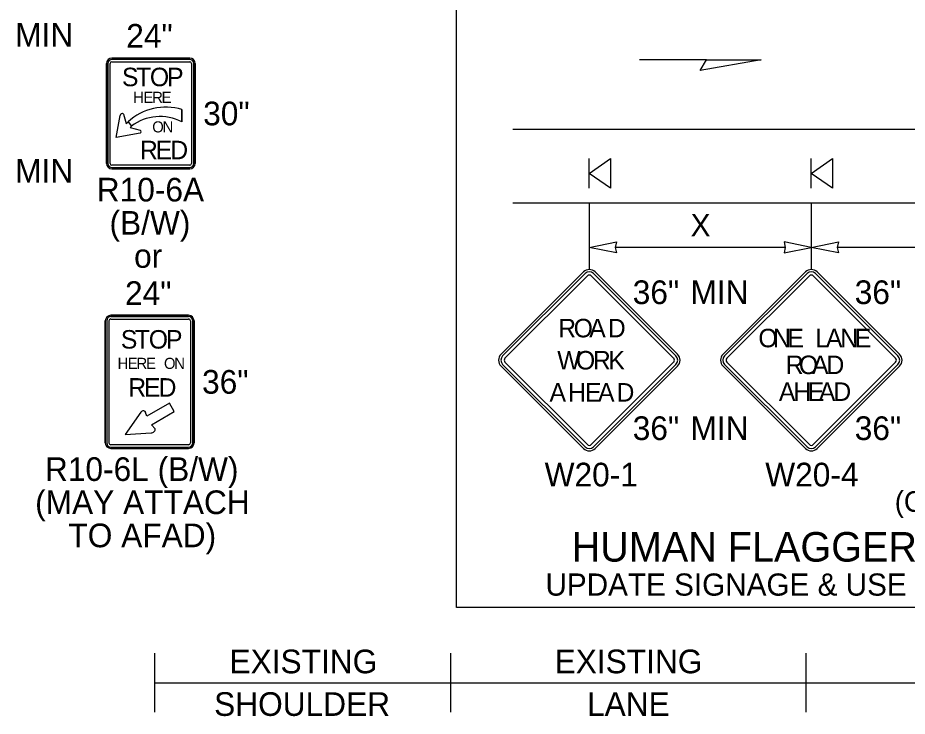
# Model space of a CAD drawing. Extents: x 99999.1 to 100095.7, y 99995 to 100010.7.
# Drawn here: x 100003.827 to 100006.832, y 100003.112 to 100005.473 of the extents above; entities that cross this region are included whole.
import ezdxf

# ---------------------------------------------------------------- set-up
doc = ezdxf.new("R2010")
doc.units = 0
for name, color, linetype in [('RD_ED_ShoulderPavedEdge', 7, 'Continuous'), ('RD_MK_LineEdgeWhite', 7, 'Continuous'), ('SH_DE_DetailHeading2Text', 7, 'Continuous'), ('TR_SN_ConstructionSigns', 7, 'Continuous'), ('TR_WZ_PortableSignMountBlk-Org', 7, 'Continuous'), ('TR_WZ_WorkZoneDetails', 7, 'Continuous'), ('TR_WZ_WorkZoneTextCurrent', 7, 'Continuous')]:
    doc.layers.add(name, color=color, linetype=linetype)

msp = doc.modelspace()

# ---------------------------------------------------------------- linework, layer by layer
at = {"layer": 'RD_ED_ShoulderPavedEdge'}
msp.add_line((100005.4994, 100004.8473), (100008.9925, 100004.8473), dxfattribs=at)
at = {"layer": 'RD_MK_LineEdgeWhite'}
msp.add_line((100005.4994, 100005.0973), (100008.9925, 100005.0973), dxfattribs=at)
at = {"layer": 'TR_SN_ConstructionSigns'}
for p, q in [((100004.4079, 100005.3373), (100004.1454, 100005.3373)), ((100004.1454, 100005.3373), (100004.4079, 100005.3373)), ((100004.4079, 100005.3373), (100004.1454, 100005.3373)), ((100004.1454, 100005.3373), (100004.4079, 100005.3373)), ((100004.4079, 100005.3326), (100004.1454, 100005.3326)), ((100004.1267, 100005.3186), (100004.1267, 100004.9811)), ((100004.1267, 100004.9811), (100004.1267, 100005.3186)), ((100004.1267, 100005.3186), (100004.1267, 100004.9811)), ((100004.1267, 100004.9811), (100004.1267, 100005.3186)), ((100004.1313, 100005.3186), (100004.1313, 100004.9811)), ((100004.1392, 100004.9811), (100004.1392, 100005.3186)), ((100004.1454, 100005.3248), (100004.4079, 100005.3248)), ((100004.4142, 100005.3186), (100004.4142, 100004.9811)), ((100004.422, 100004.9811), (100004.422, 100005.3186)), ((100004.4267, 100004.9811), (100004.4267, 100005.3186)), ((100004.4267, 100005.3186), (100004.4267, 100004.9811)), ((100004.4267, 100004.9811), (100004.4267, 100005.3186)), ((100004.4267, 100005.3186), (100004.4267, 100004.9811)), ((100004.1839, 100005.1479), (100004.1933, 100005.1154)), ((100004.3816, 100005.1635), (100004.3813, 100005.1216)), ((100004.3813, 100005.1216), (100004.3816, 100005.1635)), ((100004.1595, 100005.0686), (100004.1731, 100005.143)), ((100004.1933, 100005.1154), (100004.1996, 100005.1218)), ((100004.1996, 100005.1218), (100004.2113, 100005.1069)), ((100004.1996, 100005.1218), (100004.2113, 100005.1069)), ((100004.2113, 100005.1069), (100004.2066, 100005.1021)), ((100004.2066, 100005.1021), (100004.2408, 100005.0929)), ((100004.2406, 100005.0837), (100004.1595, 100005.0686)), ((100004.4079, 100004.9748), (100004.1454, 100004.9748)), ((100004.1454, 100004.967), (100004.4079, 100004.967)), ((100004.1454, 100004.9623), (100004.4079, 100004.9623)), ((100004.4079, 100004.9623), (100004.1454, 100004.9623)), ((100004.1454, 100004.9623), (100004.4079, 100004.9623)), ((100004.4079, 100004.9623), (100004.1454, 100004.9623)), ((100005.7382, 100004.6141), (100005.4598, 100004.3357)), ((100005.7437, 100004.6086), (100005.4653, 100004.3301)), ((100006.0509, 100004.3301), (100005.7724, 100004.6086)), ((100006.0564, 100004.3357), (100005.778, 100004.6141)), ((100006.4882, 100004.6141), (100006.2098, 100004.3357)), ((100006.4937, 100004.6086), (100006.2153, 100004.3301)), ((100006.8009, 100004.3301), (100006.5224, 100004.6086)), ((100006.8064, 100004.3357), (100006.528, 100004.6141)), ((100005.473, 100004.3224), (100005.7515, 100004.6008)), ((100005.7647, 100004.6008), (100006.0431, 100004.3224)), ((100006.223, 100004.3224), (100006.5015, 100004.6008)), ((100006.5147, 100004.6008), (100006.7931, 100004.3224)), ((100004.4041, 100004.4676), (100004.1416, 100004.4676)), ((100004.1416, 100004.4676), (100004.4041, 100004.4676)), ((100004.4041, 100004.4676), (100004.1416, 100004.4676)), ((100004.4041, 100004.4629), (100004.1416, 100004.4629)), ((100004.1416, 100004.4551), (100004.4041, 100004.4551)), ((100004.1229, 100004.4489), (100004.1229, 100004.0364)), ((100004.1229, 100004.0364), (100004.1229, 100004.4489)), ((100004.1229, 100004.4489), (100004.1229, 100004.0364)), ((100004.1276, 100004.4489), (100004.1276, 100004.0364)), ((100004.1354, 100004.0364), (100004.1354, 100004.4489)), ((100004.4104, 100004.4489), (100004.4104, 100004.0364)), ((100004.4182, 100004.0364), (100004.4182, 100004.4489)), ((100004.4229, 100004.0364), (100004.4229, 100004.4489)), ((100004.4229, 100004.4489), (100004.4229, 100004.0364)), ((100004.4229, 100004.0364), (100004.4229, 100004.4489)), ((100005.7515, 100004.0307), (100005.473, 100004.3092)), ((100006.0431, 100004.3092), (100005.7647, 100004.0307)), ((100006.5015, 100004.0307), (100006.223, 100004.3092)), ((100006.7931, 100004.3092), (100006.5147, 100004.0307)), ((100005.4598, 100004.2959), (100005.7382, 100004.0175)), ((100005.4653, 100004.3014), (100005.7437, 100004.023)), ((100005.7724, 100004.023), (100006.0509, 100004.3014)), ((100005.778, 100004.0175), (100006.0564, 100004.2959)), ((100006.2098, 100004.2959), (100006.4882, 100004.0175)), ((100006.2153, 100004.3014), (100006.4937, 100004.023)), ((100006.5224, 100004.023), (100006.8009, 100004.3014)), ((100006.528, 100004.0175), (100006.8064, 100004.2959)), ((100004.3396, 100004.1707), (100004.263, 100004.1265)), ((100004.356, 100004.1423), (100004.3396, 100004.1707)), ((100004.2424, 100004.1403), (100004.1898, 100004.0646)), ((100004.263, 100004.1265), (100004.2592, 100004.1391)), ((100004.2786, 100004.0976), (100004.356, 100004.1423)), ((100004.2909, 100004.0839), (100004.2786, 100004.0976)), ((100004.1898, 100004.0646), (100004.2776, 100004.0707)), ((100004.4041, 100004.0301), (100004.1416, 100004.0301)), ((100004.1416, 100004.0223), (100004.4041, 100004.0223)), ((100004.1416, 100004.0176), (100004.4041, 100004.0176)), ((100004.4041, 100004.0176), (100004.1416, 100004.0176)), ((100004.1416, 100004.0176), (100004.4041, 100004.0176))]:
    msp.add_line(p, q, dxfattribs=at)
for centre, radius, start, end in [((100004.1454, 100005.3186), 0.0187, 90, 180), ((100004.1454, 100005.3186), 0.0187, 90, 180), ((100004.1454, 100005.3186), 0.0187, 90, 180), ((100004.1454, 100005.3186), 0.0187, 90, 180), ((100004.1454, 100005.3186), 0.0141, 90, 180), ((100004.4079, 100005.3186), 0.0187, 0, 90), ((100004.4079, 100005.3186), 0.0187, 0, 90), ((100004.4079, 100005.3186), 0.0187, 0, 90), ((100004.4079, 100005.3186), 0.0187, 0, 90), ((100004.4079, 100005.3186), 0.0141, 0, 90), ((100004.1454, 100005.3186), 0.00625, 90, 180), ((100004.4079, 100005.3186), 0.00625, 0, 90), ((100004.3279, 100004.9804), 0.1909, 73.6434, 132.2131), ((100004.3279, 100004.9804), 0.1909, 73.6434, 132.2131), ((100004.3078, 100004.981), 0.1586, 62.4149, 127.4769), ((100004.3078, 100004.981), 0.1586, 62.4149, 127.4769), ((100004.1454, 100004.9811), 0.0187, 180, 270), ((100004.1454, 100004.9811), 0.0187, 180, 270), ((100004.1454, 100004.9811), 0.0187, 180, 270), ((100004.1454, 100004.9811), 0.0187, 180, 270), ((100004.1454, 100004.9811), 0.0141, 180, 270), ((100004.1454, 100004.9811), 0.00625, 180, 270), ((100004.4079, 100004.9811), 0.0187, 270, 0), ((100004.4079, 100004.9811), 0.0187, 270, 0), ((100004.4079, 100004.9811), 0.0187, 270, 0), ((100004.4079, 100004.9811), 0.0141, 270, 0), ((100004.4079, 100004.9811), 0.00625, 270, 0), ((100004.4079, 100004.9811), 0.0187, 270, 0), ((100005.7581, 100004.5942), 0.0281, 45, 135), ((100005.7581, 100004.5942), 0.0203, 45, 135), ((100006.5081, 100004.5942), 0.0281, 45, 135), ((100006.5081, 100004.5942), 0.0203, 45, 135), ((100005.7581, 100004.5942), 0.00937, 45, 135), ((100006.5081, 100004.5942), 0.00937, 45, 135), ((100004.1416, 100004.4489), 0.0187, 90, 180), ((100004.1416, 100004.4489), 0.0187, 90, 180), ((100004.1416, 100004.4489), 0.0187, 90, 180), ((100004.1416, 100004.4489), 0.0141, 90, 180), ((100004.1416, 100004.4489), 0.00625, 90, 180), ((100004.4041, 100004.4489), 0.0187, 0, 90), ((100004.4041, 100004.4489), 0.0187, 0, 90), ((100004.4041, 100004.4489), 0.0187, 0, 90), ((100004.4041, 100004.4489), 0.0141, 0, 90), ((100004.4041, 100004.4489), 0.00625, 0, 90), ((100005.4797, 100004.3158), 0.0281, 135, 225), ((100006.0365, 100004.3158), 0.0281, 315, 45), ((100006.2297, 100004.3158), 0.0281, 135, 225), ((100006.7865, 100004.3158), 0.0281, 315, 45), ((100005.4797, 100004.3158), 0.0203, 135, 225), ((100005.4797, 100004.3158), 0.00937, 135, 225), ((100006.0365, 100004.3158), 0.00937, 315, 45), ((100006.0365, 100004.3158), 0.0203, 315, 45), ((100006.2297, 100004.3158), 0.0203, 135, 225), ((100006.2297, 100004.3158), 0.00937, 135, 225), ((100006.7865, 100004.3158), 0.00937, 315, 45), ((100006.7865, 100004.3158), 0.0203, 315, 45), ((100004.1416, 100004.0364), 0.0187, 180, 270), ((100004.1416, 100004.0364), 0.0187, 180, 270), ((100004.1416, 100004.0364), 0.0187, 180, 270), ((100004.1416, 100004.0364), 0.0141, 180, 270), ((100004.1416, 100004.0364), 0.00625, 180, 270), ((100004.4041, 100004.0364), 0.0187, 270, 0), ((100004.4041, 100004.0364), 0.0187, 270, 0), ((100004.4041, 100004.0364), 0.0187, 270, 0), ((100004.4041, 100004.0364), 0.0141, 270, 0), ((100004.4041, 100004.0364), 0.00625, 270, 0), ((100005.7581, 100004.0374), 0.0281, 225, 315), ((100005.7581, 100004.0374), 0.0203, 225, 315), ((100005.7581, 100004.0374), 0.00937, 225, 315), ((100006.5081, 100004.0374), 0.0281, 225, 315), ((100006.5081, 100004.0374), 0.0203, 225, 315), ((100006.5081, 100004.0374), 0.00937, 225, 315)]:
    msp.add_arc(centre, radius, start, end, dxfattribs=at)
for centre, major_axis, ratio, start_param, end_param in [((100004.1795, 100005.1431), (-0.00647, -0.00009), 0.989437, 3.962549, 6.283185), ((100004.2384, 100005.0883), (-0.0046, 0.00239), 0.999053, 2.490568, 4.712389), ((100004.2492, 100004.136), (0.00934, 0.00539), 0.700347, 5.977036, 8.198856), ((100004.2816, 100004.0789), (-0.00913, -0.00527), 0.700347, 0.771965, 3.092601)]:
    msp.add_ellipse(centre, major_axis=major_axis, ratio=ratio, start_param=start_param, end_param=end_param, dxfattribs=at)
at = {"layer": 'TR_WZ_PortableSignMountBlk-Org'}
for p, q in [((100005.7581, 100004.8974), (100005.7581, 100004.9974)), ((100006.5081, 100004.8974), (100006.5081, 100004.9974))]:
    msp.add_line(p, q, dxfattribs=at)
for points in [[(100005.7581, 100004.9473), (100005.8299, 100004.9974), (100005.8299, 100004.8974)], [(100006.5081, 100004.9473), (100006.5799, 100004.9974), (100006.5799, 100004.8974)]]:
    msp.add_lwpolyline(points, close=True, dxfattribs=at)
at = {"layer": 'TR_WZ_WorkZoneDetails'}
for p, q in [((100006.154, 100005.331), (100005.9279, 100005.331)), ((100005.7581, 100004.8476), (100005.7581, 100004.6223)), ((100006.5081, 100004.8473), (100006.5081, 100004.6223)), ((100006.4202, 100004.6973), (100005.846, 100004.6973)), ((100007.1702, 100004.6973), (100006.596, 100004.6973)), ((100004.2907, 100003.1255), (100004.2907, 100003.3255)), ((100005.2907, 100003.1255), (100005.2907, 100003.3255)), ((100006.4907, 100003.1255), (100006.4907, 100003.3255)), ((100004.2907, 100003.2255), (100005.2907, 100003.2255)), ((100005.2907, 100003.2255), (100006.4907, 100003.2255)), ((100006.4907, 100003.2255), (100007.6907, 100003.2255))]:
    msp.add_line(p, q, dxfattribs=at)
for points in [[(100006.3382, 100005.331), (100006.1331, 100005.2949), (100006.154, 100005.331)], [(100005.7581, 100004.6973), (100005.8502, 100004.7154), (100005.846, 100004.6973), (100005.8502, 100004.6793)], [(100006.5081, 100004.6973), (100006.4159, 100004.7154), (100006.4202, 100004.6973), (100006.4159, 100004.6793)], [(100006.5081, 100004.6973), (100006.6002, 100004.7154), (100006.596, 100004.6973), (100006.6002, 100004.6793)]]:
    msp.add_lwpolyline(points, close=True, dxfattribs=at)
at = {"layer": 'TR_WZ_WorkZoneTextCurrent'}
msp.add_lwpolyline([(100005.3092, 100005.5823), (100009.1102, 100005.5823), (100009.1102, 100003.4799), (100005.3092, 100003.4799)], close=True, dxfattribs=at)

# ---------------------------------------------------------------- texts
at = {"layer": 'SH_DE_DetailHeading2Text'}
msp.add_text('HUMAN FLAGGER SUBSTITUTION', height=0.1, rotation=360, dxfattribs=at).set_placement((100005.6986, 100003.6349))
at = {"layer": 'TR_SN_ConstructionSigns'}
for s, height, p in [('MIN', 0.08, (100003.8184, 100005.3756)), ('24"', 0.08, (100004.1936, 100005.3723)), ('30"', 0.08, (100004.4536, 100005.1098)), ('MIN', 0.08, (100003.8184, 100004.916)), ('R10-6A', 0.08, (100004.094, 100004.8523)), ('(B/W)', 0.08, (100004.1371, 100004.7403)), ('or', 0.08, (100004.2201, 100004.6283)), ('24"', 0.08, (100004.1895, 100004.5026)), ('36"', 0.08, (100005.9048, 100004.5056)), ('MIN', 0.08, (100006.0999, 100004.5056)), ('36"', 0.08, (100006.6548, 100004.5056)), ('36"', 0.08, (100004.4498, 100004.2026)), ('36"', 0.08, (100005.9048, 100004.046)), ('MIN', 0.08, (100006.0999, 100004.046)), ('36"', 0.08, (100006.6548, 100004.046)), ('R10-6L (B/W)', 0.08, (100003.919, 100003.9076)), ('W20-1', 0.08, (100005.6072, 100003.8892)), ('W20-4', 0.08, (100006.3526, 100003.8892)), ('(MAY ATTACH', 0.08, (100003.8858, 100003.7956)), ('(OPTIONAL', 0.07, (100006.79, 100003.8032)), ('TO AFAD)', 0.08, (100003.9982, 100003.6836))]:
    msp.add_text(s, height=height, rotation=360, dxfattribs=at).set_placement(p)
for s, height, p in [('S', 0.0625, (100004.1792, 100005.242)), ('T', 0.0625, (100004.2267, 100005.242)), ('O', 0.0625, (100004.2735, 100005.242)), ('P', 0.0625, (100004.3317, 100005.242)), ('H', 0.0375, (100004.217, 100005.1858)), ('E', 0.0375, (100004.2515, 100005.1858)), ('R', 0.0375, (100004.2812, 100005.1858)), ('E', 0.0375, (100004.313, 100005.1858)), ('O', 0.0375, (100004.2815, 100005.0858)), ('N', 0.0375, (100004.3164, 100005.0858)), ('R', 0.0625, (100004.2399, 100004.9951)), ('E', 0.0625, (100004.293, 100004.9951)), ('D', 0.0625, (100004.3424, 100004.9951)), ('R', 0.0625, (100005.653, 100004.3931)), ('O', 0.0625, (100005.7052, 100004.3931)), ('A', 0.0625, (100005.7579, 100004.3931)), ('D', 0.0625, (100005.8207, 100004.3931)), ('S', 0.0625, (100004.1754, 100004.3551)), ('T', 0.0625, (100004.2229, 100004.3551)), ('O', 0.0625, (100004.2698, 100004.3551)), ('P', 0.0625, (100004.3279, 100004.3551)), ('O', 0.0625, (100006.3293, 100004.3595)), ('N', 0.0625, (100006.3787, 100004.3595)), ('E', 0.0625, (100006.4275, 100004.3595)), ('L', 0.0625, (100006.5218, 100004.3595)), ('A', 0.0625, (100006.5575, 100004.3595)), ('N', 0.0625, (100006.6062, 100004.3595)), ('E', 0.0625, (100006.655, 100004.3595)), ('W', 0.0625, (100005.6498, 100004.2845)), ('O', 0.0625, (100005.713, 100004.2845)), ('R', 0.0625, (100005.7702, 100004.2845)), ('K', 0.0625, (100005.8227, 100004.2845)), ('H', 0.0375, (100004.1643, 100004.2864)), ('E', 0.0375, (100004.1988, 100004.2864)), ('R', 0.0375, (100004.2284, 100004.2864)), ('E', 0.0375, (100004.2603, 100004.2864)), ('O', 0.0375, (100004.3211, 100004.2864)), ('N', 0.0375, (100004.3559, 100004.2864)), ('R', 0.0625, (100006.4218, 100004.2689)), ('O', 0.0625, (100006.4662, 100004.2689)), ('A', 0.0625, (100006.5106, 100004.2689)), ('D', 0.0625, (100006.5593, 100004.2689)), ('R', 0.0625, (100004.2004, 100004.1926)), ('E', 0.0625, (100004.2535, 100004.1926)), ('D', 0.0625, (100004.3029, 100004.1926)), ('A', 0.0625, (100005.6237, 100004.176)), ('H', 0.0625, (100005.6862, 100004.176)), ('E', 0.0625, (100005.7437, 100004.176)), ('A', 0.0625, (100005.7875, 100004.176)), ('D', 0.0625, (100005.85, 100004.176)), ('A', 0.0625, (100006.3987, 100004.1783)), ('H', 0.0625, (100006.4475, 100004.1783)), ('E', 0.0625, (100006.4962, 100004.1783)), ('A', 0.0625, (100006.5337, 100004.1783)), ('D', 0.0625, (100006.5825, 100004.1783))]:
    msp.add_text(s, height=height, dxfattribs=at).set_placement(p)
at = {"layer": 'TR_WZ_WorkZoneDetails'}
for s, p in [('EXISTING', (100004.5424, 100003.2575)), ('EXISTING', (100005.6409, 100003.2575)), ('SHOULDER', (100004.4905, 100003.1135)), ('LANE', (100005.7503, 100003.1135))]:
    msp.add_text(s, height=0.08, rotation=360, dxfattribs=at).set_placement(p)
at = {"layer": 'TR_WZ_WorkZoneTextCurrent'}
msp.add_text('X', height=0.075, rotation=360, dxfattribs=at).set_placement((100006.1005, 100004.7348))
msp.add_text('UPDATE SIGNAGE & USE STOP/SLOW PADDLE', height=0.075, dxfattribs=at).set_placement((100005.6099, 100003.5199))

doc.saveas('drawing.dxf')
